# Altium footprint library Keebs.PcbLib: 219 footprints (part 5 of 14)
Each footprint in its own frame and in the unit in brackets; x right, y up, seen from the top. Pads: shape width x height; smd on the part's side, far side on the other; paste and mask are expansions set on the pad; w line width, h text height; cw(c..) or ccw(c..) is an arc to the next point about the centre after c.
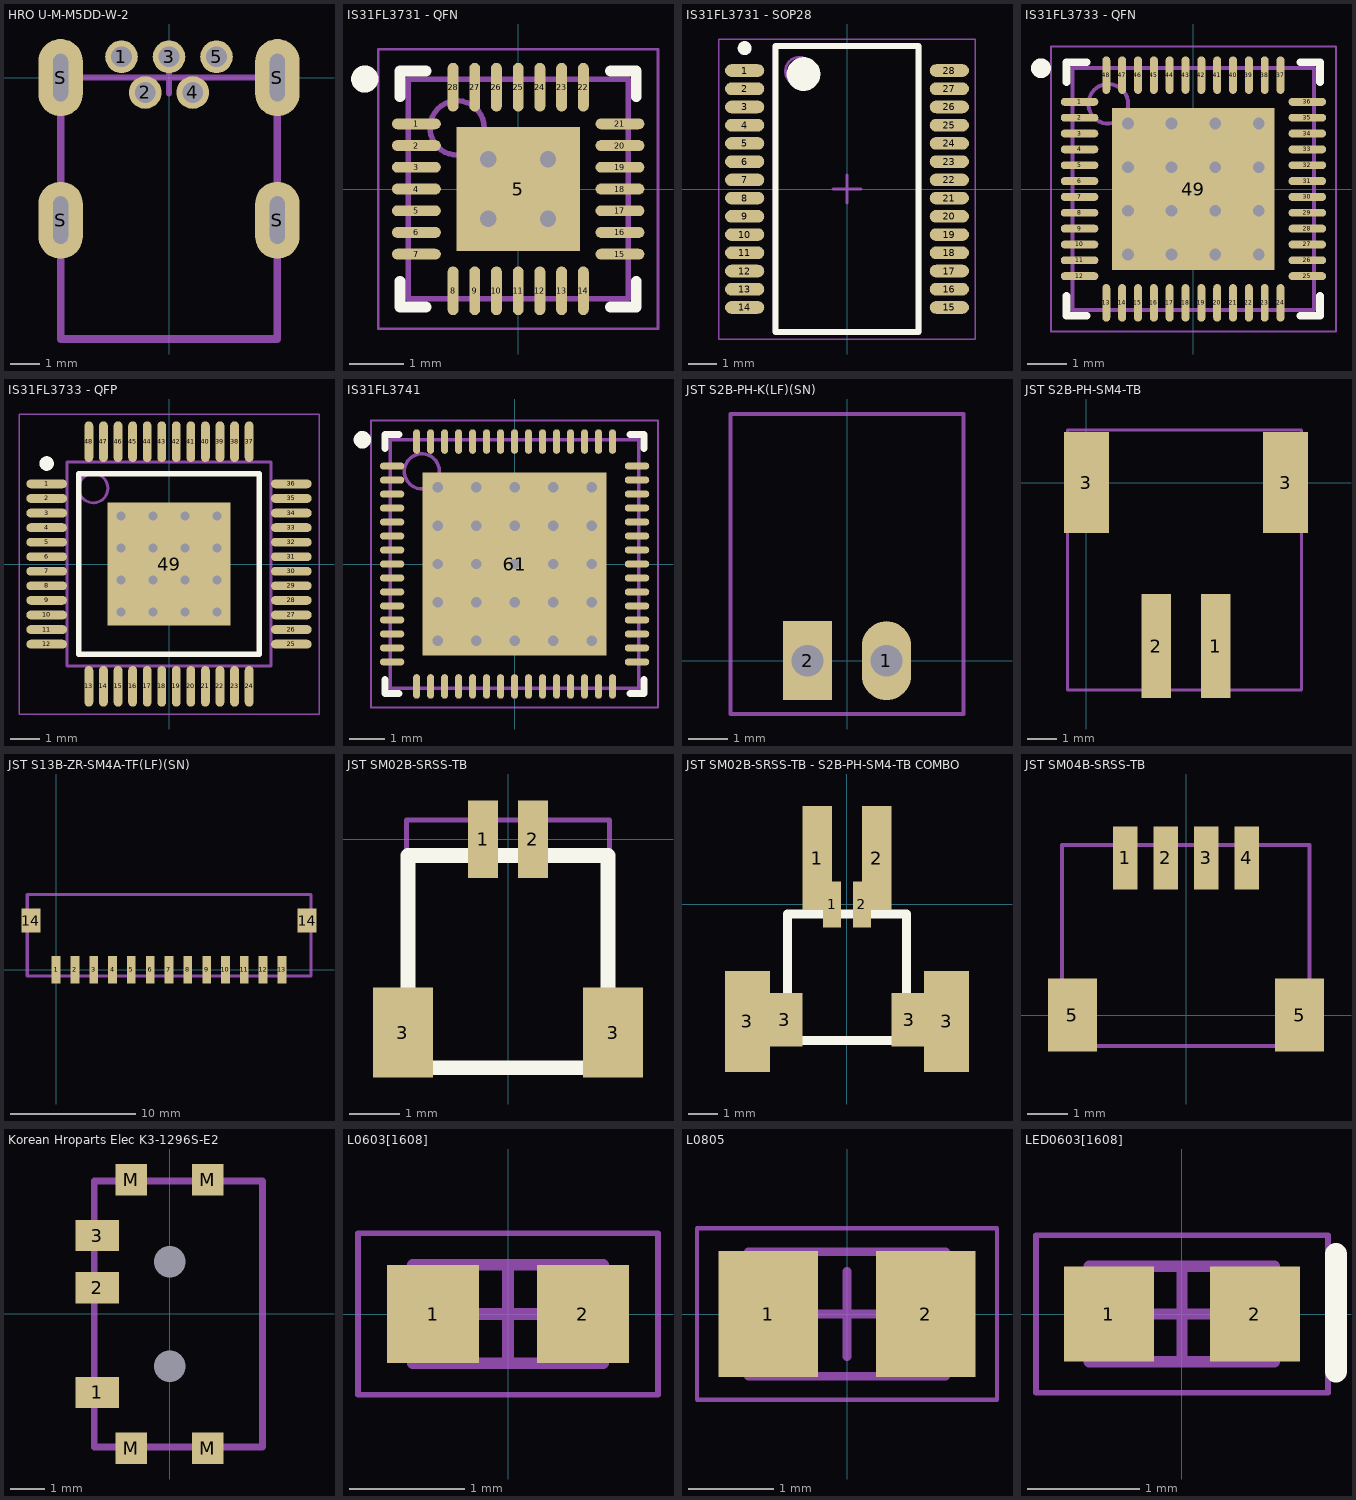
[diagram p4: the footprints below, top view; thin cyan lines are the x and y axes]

## HRO U-M-M5DD-W-2 [mm]
pads (9):
  round 1.1 hole 0.7: 1(-1.6,0.7) 2(-0.8,-0.5) 3(0,0.7) 4(0.8,-0.5) 5(1.6,0.7)
  oval 1.5x2.6 hole 0.5 slot 1.6 at 90 deg: S(-3.65,-4.8) S(-3.65,0) S(3.65,-4.8) S(3.65,0)
Mechanical 13:
  lines w0.2: -3.65,-8.8 3.65,-8.8 3.65,0 -3.65,0 -3.65,-8.8
  text ".Designator" at 1.905,-3.556 h0.35
Mechanical 15:
  lines w0.2: -0.533,0 0,0 ; 0,0.533 0,0 ; 0.533,0 0,0 ; 0,0 0,-0.533 0,0
  lines w0.254: -3.65,0 -3.65,-8.8 3.65,-8.8 3.65,0

## IS31FL3731 - QFN [mm]
height 0.8
pads (29):
  oval 0.9x0.2 smd: 1(-1.875,1.2) 2(-1.875,0.8) 3(-1.875,0.4) 4(-1.875,0) 5(-1.875,-0.4) 6(-1.875,-0.8) 7(-1.875,-1.2) 15(1.875,-1.2) 16(1.875,-0.8) 17(1.875,-0.4) 18(1.875,0) 19(1.875,0.4) 20(1.875,0.8) 21(1.875,1.2)
  rect 2.28x2.28 smd: 5(0,0)
  oval 0.2x0.9 smd: 8(-1.2,-1.875) 9(-0.8,-1.875) 10(-0.4,-1.875) 11(0,-1.875) 12(0.4,-1.875) 13(0.8,-1.875) 14(1.2,-1.875) 22(1.2,1.875) 23(0.8,1.875) 24(0.4,1.875) 25(0,1.875) 26(-0.4,1.875) 27(-0.8,1.875) 28(-1.2,1.875)
via 0.55,-0.55 diameter 0.6 hole 0.3
via -0.55,-0.55 diameter 0.6 hole 0.3
via 0.55,0.55 diameter 0.6 hole 0.3
via -0.55,0.55 diameter 0.6 hole 0.3
Top Overlay:
  circle w0.25: c-2.825,2.025 r0.125
  lines w0.2: -2.175,-1.7 -2.175,-2.175 -1.7,-2.175 ; -2.175,1.7 -2.175,2.175 -1.7,2.175 ; 1.7,-2.175 2.175,-2.175 2.175,-1.7 ; 1.7,2.175 2.175,2.175 2.175,1.7
Mechanical 13:
  circle w0.1: c-1.125,1.125 r0.5
  lines w0.1: -2.025,-2.025 2.025,-2.025 2.025,2.025 -2.025,2.025 -2.025,-2.025
  text ".Designator" at -1.905,-0.254 h0.5
Mechanical 15:
  lines w0.05: -2.575,-2.575 2.575,-2.575 2.575,2.575 -2.575,2.575 -2.575,-2.575
  lines w0.1: -0.5,0 0.5,0 ; 0,-0.5 0,0.5
3D body "IS31FL3731 - QFN.step": height 0.8, standoff 0, extent -2.026,-2.026 2.026,2.026

## IS31FL3731 - SOP28 [mm] "IS31FL3731 - SOP28"
height 1.8
pads (28):
  oval 1.4x0.45 smd: 1(-3.65,4.225) 2(-3.65,3.575) 3(-3.65,2.925) 4(-3.65,2.275) 5(-3.65,1.625) 6(-3.65,0.975) 7(-3.65,0.325) 8(-3.65,-0.325) 9(-3.65,-0.975) 10(-3.65,-1.625) 11(-3.65,-2.275) 12(-3.65,-2.925) 13(-3.65,-3.575) 14(-3.65,-4.225) 15(3.65,-4.225) 16(3.65,-3.575) 17(3.65,-2.925) 18(3.65,-2.275) 19(3.65,-1.625) 20(3.65,-0.975) 21(3.65,-0.325) 22(3.65,0.325) 23(3.65,0.975) 24(3.65,1.625) 25(3.65,2.275) 26(3.65,2.925) 27(3.65,3.575) 28(3.65,4.225)
Top Overlay:
  circle w0.25: c-3.65,5.025 r0.125
  circle w0.6: c-1.55,4.1 r0.3
  lines w0.2: -2.55,-5.1 -2.55,5.1 2.55,5.1 2.55,-5.1 -2.55,-5.1
Mechanical 13:
  circle w0.1: c-1.7,4.2 r0.5
  lines w0.1: -2.6,-5.1 -2.6,5.1 2.6,5.1 2.6,-5.1 -2.6,-5.1
  text ".Designator" at -0.254,2.159 h0.5
Mechanical 15:
  lines w0.05: -4.575,-5.35 -4.575,5.35 4.575,5.35 4.575,-5.35 -4.575,-5.35
  lines w0.1: -0.5,0 0.5,0 ; 0,-0.5 0,0.5
3D body "IS31FL3731 - SOP28.step": height 1.8, standoff 0, extent -3.9,-5.1 3.9,5.1

## IS31FL3733 - QFN [mm]
height 0.8
pads (49):
  oval 0.95x0.2 smd: 1(-2.875,2.2) 2(-2.875,1.8) 3(-2.875,1.4) 4(-2.875,1) 5(-2.875,0.6) 6(-2.875,0.2) 7(-2.875,-0.2) 8(-2.875,-0.6) 9(-2.875,-1) 10(-2.875,-1.4) 11(-2.875,-1.8) 12(-2.875,-2.2) 25(2.875,-2.2) 26(2.875,-1.8) 27(2.875,-1.4) 28(2.875,-1) 29(2.875,-0.6) 30(2.875,-0.2) 31(2.875,0.2) 32(2.875,0.6) 33(2.875,1) 34(2.875,1.4) 35(2.875,1.8) 36(2.875,2.2)
  oval 0.2x0.95 smd: 13(-2.2,-2.875) 14(-1.8,-2.875) 15(-1.4,-2.875) 16(-1,-2.875) 17(-0.6,-2.875) 18(-0.2,-2.875) 19(0.2,-2.875) 20(0.6,-2.875) 21(1,-2.875) 22(1.4,-2.875) 23(1.8,-2.875) 24(2.2,-2.875) 37(2.2,2.875) 38(1.8,2.875) 39(1.4,2.875) 40(1,2.875) 41(0.6,2.875) 42(0.2,2.875) 43(-0.2,2.875) 44(-0.6,2.875) 45(-1,2.875) 46(-1.4,2.875) 47(-1.8,2.875) 48(-2.2,2.875)
  rect 4.1x4.1 smd: 49(0,0)
via -1.65,1.65 diameter 0.6 hole 0.3
via -0.55,1.65 diameter 0.6 hole 0.3
via 0.55,1.65 diameter 0.6 hole 0.3
via 1.65,1.65 diameter 0.6 hole 0.3
via -1.65,0.55 diameter 0.6 hole 0.3
via -0.55,0.55 diameter 0.6 hole 0.3
via 0.55,0.55 diameter 0.6 hole 0.3
via 1.65,0.55 diameter 0.6 hole 0.3
via -1.65,-0.55 diameter 0.6 hole 0.3
via -0.55,-0.55 diameter 0.6 hole 0.3
via 0.55,-0.55 diameter 0.6 hole 0.3
via 1.65,-0.55 diameter 0.6 hole 0.3
via -1.65,-1.65 diameter 0.6 hole 0.3
via -0.55,-1.65 diameter 0.6 hole 0.3
via 0.55,-1.65 diameter 0.6 hole 0.3
via 1.65,-1.65 diameter 0.6 hole 0.3
Top Overlay:
  circle w0.25: c-3.85,3.05 r0.125
  lines w0.2: -3.2,-2.7 -3.2,-3.2 -2.7,-3.2 ; -3.2,2.7 -3.2,3.2 -2.7,3.2 ; 2.7,-3.2 3.2,-3.2 3.2,-2.7 ; 2.7,3.2 3.2,3.2 3.2,2.7
Mechanical 13:
  circle w0.1: c-2.15,2.15 r0.5
  lines w0.1: -3.05,-3.05 -3.05,3.05 3.05,3.05 3.05,-3.05 -3.05,-3.05
  text ".Designator" at -2.286,-0.254 h0.5
Mechanical 15:
  lines w0.05: -3.6,-3.6 -3.6,3.6 3.6,3.6 3.6,-3.6 -3.6,-3.6
  lines w0.1: -0.5,0 0.5,0 ; 0,-0.5 0,0.5
3D body "IS31FL3733 - QFN.step": height 0.8, standoff 0, extent -3.051,-3.051 3.051,3.051

## IS31FL3733 - QFP [mm]
height 1.2
pads (49):
  oval 1.4x0.3 smd: 1(-4.2,2.75) 2(-4.2,2.25) 3(-4.2,1.75) 4(-4.2,1.25) 5(-4.2,0.75) 6(-4.2,0.25) 7(-4.2,-0.25) 8(-4.2,-0.75) 9(-4.2,-1.25) 10(-4.2,-1.75) 11(-4.2,-2.25) 12(-4.2,-2.75) 25(4.2,-2.75) 26(4.2,-2.25) 27(4.2,-1.75) 28(4.2,-1.25) 29(4.2,-0.75) 30(4.2,-0.25) 31(4.2,0.25) 32(4.2,0.75) 33(4.2,1.25) 34(4.2,1.75) 35(4.2,2.25) 36(4.2,2.75)
  oval 0.3x1.4 smd: 13(-2.75,-4.2) 14(-2.25,-4.2) 15(-1.75,-4.2) 16(-1.25,-4.2) 17(-0.75,-4.2) 18(-0.25,-4.2) 19(0.25,-4.2) 20(0.75,-4.2) 21(1.25,-4.2) 22(1.75,-4.2) 23(2.25,-4.2) 24(2.75,-4.2) 37(2.75,4.2) 38(2.25,4.2) 39(1.75,4.2) 40(1.25,4.2) 41(0.75,4.2) 42(0.25,4.2) 43(-0.25,4.2) 44(-0.75,4.2) 45(-1.25,4.2) 46(-1.75,4.2) 47(-2.25,4.2) 48(-2.75,4.2)
  rect 4.21x4.21 smd: 49(0,0)
via -1.65,1.65 diameter 0.6 hole 0.3
via -0.55,1.65 diameter 0.6 hole 0.3
via 0.55,1.65 diameter 0.6 hole 0.3
via 1.65,1.65 diameter 0.6 hole 0.3
via -1.65,0.55 diameter 0.6 hole 0.3
via -0.55,0.55 diameter 0.6 hole 0.3
via 0.55,0.55 diameter 0.6 hole 0.3
via 1.65,0.55 diameter 0.6 hole 0.3
via -1.65,-0.55 diameter 0.6 hole 0.3
via -0.55,-0.55 diameter 0.6 hole 0.3
via 0.55,-0.55 diameter 0.6 hole 0.3
via 1.65,-0.55 diameter 0.6 hole 0.3
via -1.65,-1.65 diameter 0.6 hole 0.3
via -0.55,-1.65 diameter 0.6 hole 0.3
via 0.55,-1.65 diameter 0.6 hole 0.3
via 1.65,-1.65 diameter 0.6 hole 0.3
Top Overlay:
  circle w0.25: c-4.2,3.45 r0.125
  lines w0.2: -3.1,-3.1 -3.1,3.1 3.1,3.1 3.1,-3.1 -3.1,-3.1
Mechanical 13:
  circle w0.1: c-2.6,2.6 r0.5
  lines w0.1: -3.5,-3.5 -3.5,3.5 3.5,3.5 3.5,-3.5 -3.5,-3.5
  text ".Designator" at -2.667,0 h0.5
Mechanical 15:
  lines w0.05: -5.15,-5.15 -5.15,5.15 5.15,5.15 5.15,-5.15 -5.15,-5.15
  lines w0.1: -0.5,0 0.5,0 ; 0,-0.5 0,0.5
3D body "IS31FL3733 - QFP.step": height 1.2, standoff 0, extent -4.5,-4.5 4.5,4.5

## IS31FL3741 [mm]
height 0.9
pads (61):
  oval 0.7x0.2 smd: 1(-3.5,2.8) 2(-3.5,2.4) 3(-3.5,2) 4(-3.5,1.6) 5(-3.5,1.2) 6(-3.5,0.8) 7(-3.5,0.4) 8(-3.5,0) 9(-3.5,-0.4) 10(-3.5,-0.8) 11(-3.5,-1.2) 12(-3.5,-1.6) 13(-3.5,-2) 14(-3.5,-2.4) 15(-3.5,-2.8) 31(3.5,-2.8) 32(3.5,-2.4) 33(3.5,-2) 34(3.5,-1.6) 35(3.5,-1.2) 36(3.5,-0.8) 37(3.5,-0.4) 38(3.5,0) 39(3.5,0.4) 40(3.5,0.8) 41(3.5,1.2) 42(3.5,1.6) 43(3.5,2) 44(3.5,2.4) 45(3.5,2.8)
  oval 0.2x0.7 smd: 16(-2.8,-3.5) 17(-2.4,-3.5) 18(-2,-3.5) 19(-1.6,-3.5) 20(-1.2,-3.5) 21(-0.8,-3.5) 22(-0.4,-3.5) 23(0,-3.5) 24(0.4,-3.5) 25(0.8,-3.5) 26(1.2,-3.5) 27(1.6,-3.5) 28(2,-3.5) 29(2.4,-3.5) 30(2.8,-3.5) 46(2.8,3.5) 47(2.4,3.5) 48(2,3.5) 49(1.6,3.5) 50(1.2,3.5) 51(0.8,3.5) 52(0.4,3.5) 53(0,3.5) 54(-0.4,3.5) 55(-0.8,3.5) 56(-1.2,3.5) 57(-1.6,3.5) 58(-2,3.5) 59(-2.4,3.5) 60(-2.8,3.5)
  rect 5.25x5.24 smd: 61(0,0)
via -2.2,2.2 diameter 0.6 hole 0.3
via -1.1,2.2 diameter 0.6 hole 0.3
via 0,2.2 diameter 0.6 hole 0.3
via 1.1,2.2 diameter 0.6 hole 0.3
via 2.2,2.2 diameter 0.6 hole 0.3
via -2.2,1.1 diameter 0.6 hole 0.3
via -1.1,1.1 diameter 0.6 hole 0.3
via 0,1.1 diameter 0.6 hole 0.3
via 1.1,1.1 diameter 0.6 hole 0.3
via 2.2,1.1 diameter 0.6 hole 0.3
via -2.2,0 diameter 0.6 hole 0.3
via -1.1,0 diameter 0.6 hole 0.3
via 0,0 diameter 0.6 hole 0.3
via 1.1,0 diameter 0.6 hole 0.3
via 2.2,0 diameter 0.6 hole 0.3
via -2.2,-1.1 diameter 0.6 hole 0.3
via -1.1,-1.1 diameter 0.6 hole 0.3
via 0,-1.1 diameter 0.6 hole 0.3
via 1.1,-1.1 diameter 0.6 hole 0.3
via 2.2,-1.1 diameter 0.6 hole 0.3
via -2.2,-2.2 diameter 0.6 hole 0.3
via -1.1,-2.2 diameter 0.6 hole 0.3
via 0,-2.2 diameter 0.6 hole 0.3
via 1.1,-2.2 diameter 0.6 hole 0.3
via 2.2,-2.2 diameter 0.6 hole 0.3
Top Overlay:
  circle w0.25: c-4.35,3.55 r0.125
  lines w0.2: -3.7,-3.3 -3.7,-3.7 -3.3,-3.7 ; -3.7,3.3 -3.7,3.7 -3.3,3.7 ; 3.3,-3.7 3.7,-3.7 3.7,-3.3 ; 3.3,3.7 3.7,3.7 3.7,3.3
Mechanical 13:
  circle w0.1: c-2.65,2.65 r0.5
  lines w0.1: -3.55,-3.55 -3.55,3.55 3.55,3.55 3.55,-3.55 -3.55,-3.55
  text ".Designator" at -2.413,-0.127 h0.5
Mechanical 15:
  lines w0.05: -4.1,-4.1 -4.1,4.1 4.1,4.1 4.1,-4.1 -4.1,-4.1
  lines w0.1: -0.5,0 0.5,0 ; 0,-0.5 0,0.5
3D body "IS31FL3741.step": height 0.9, standoff 0, extent -3.56,-3.56 3.56,3.56

## JST S2B-PH-K(LF)(SN) [mm]
pads (2):
  oval 1.25x2 hole 0.8: 1(1,0)
  rect 1.25x2 hole 0.8: 2(-1,0)
Mechanical 13:
  lines w0.1: -2.95,-1.35 2.95,-1.35 2.95,6.25 -2.95,6.25 -2.95,-1.35
  text ".Designator" at -1.834,2.664 h0.35
3D body "S2B-PH-K-S.STEP": height 4.8, standoff -3.4, extent -2.95,-1.35 2.95,6.25

## JST S2B-PH-SM4-TB [mm]
pads (4):
  rect 1x3.5 smd: 1(4.35,-5.5) 2(2.35,-5.5)
  rect 1.5x3.4 smd: 3(0,0) 3(6.7,0)
Mechanical 13:
  lines w0.1: -0.635,-6.985 -0.635,1.778 7.239,1.778 7.239,-6.985 -0.635,-6.985
  text ".Designator" at 1.742,-2.638 h0.35
3D body "S2B-PH-SM4-TB.STEP": height 5.6, standoff 0, extent -0.648,-6.949 7.252,1.651

## JST S13B-ZR-SM4A-TF(LF)(SN) [mm]
pads (15):
  rect 0.7x2.2 smd: 1(0,0) 2(1.5,0) 3(3,0) 4(4.5,0) 5(6,0) 6(7.5,0) 7(9,0) 8(10.5,0) 9(12,0) 10(13.5,0) 11(15,0) 12(16.5,0) 13(18,0)
  rect 1.5x1.9 smd: 14(-2,3.9) 14(20,3.9)
Mechanical 13:
  lines w0.254: -2.286,-0.508 -2.286,5.969 20.32,5.969 20.32,-0.508 -2.286,-0.508
  text ".Designator" at 6.35,3.175 h0.5
3D body "S13B-ZR-SM4A-TF.STEP": height 3.7, standoff 0, extent -2.233,-0.531 20.267,5.969

## JST SM02B-SRSS-TB [mm]
pads (4):
  rect 0.6x1.55 smd: 1(-0.5,0) 2(0.5,0)
  rect 1.2x1.8 smd: 3(-2.1,-3.875) 3(2.1,-3.875)
Top Overlay:
  lines w0.3: -2,-4.575 2,-4.575 2,-0.325 -2,-0.325 -2,-4.575
Mechanical 13:
  lines w0.1: -2.032,-4.572 -2.032,0.381 2.032,0.381 2.032,-4.572 -2.032,-4.572
  text ".Designator" at -1.651,-2.286 h0.5
3D body "JST_SM02B-SRSS-TB.step": height 3, standoff 0, extent -1.994,-4.575 1.994,0.412

## JST SM02B-SRSS-TB - S2B-PH-SM4-TB COMBO [mm]
pads (8):
  rect 1x3.5 smd: 1(-1,1.563) 2(1,1.563)
  rect 0.6x1.55 smd: 1(-0.5,0) 2(0.5,0)
  rect 1.5x3.4 smd: 3(-3.35,-3.937) 3(3.35,-3.937)
  rect 1.2x1.8 smd: 3(-2.1,-3.875) 3(2.1,-3.875)
Top Overlay:
  lines w0.3: -2,-4.575 -2,-0.325 2,-0.325 2,-4.575 -2,-4.575
Mechanical 13:
  lines w0.1: -2,-4.575 2,-4.575 2,-0.325 -2,-0.325 -2,-4.575
  text ".Designator" at -1.651,-2.921 h0.5
3D body "JST_SM02B-SRSS-TB.step": height 3, standoff 0, extent -1.994,-4.575 1.994,0.412

## JST SM04B-SRSS-TB [mm]
pads (6):
  rect 0.6x1.55 smd: 1(-1.5,3.875) 2(-0.5,3.875) 3(0.5,3.875) 4(1.5,3.875)
  rect 1.2x1.8 smd: 5(-2.8,0) 5(2.8,0)
Mechanical 13:
  lines w0.1: -3.054,-0.762 3.042,-0.762 3.042,4.191 -3.054,4.191 -3.054,-0.762
  text ".Designator" at -2.673,1.524 h0.7
3D body "SM04B-SRSS-TB.STEP": height 2.96, standoff 0, extent -3.006,-0.762 2.994,4.188

## Korean Hroparts Elec K3-1296S-E2 [mm]
pads (9):
  rect 1.25x0.9 smd: 1(-2.075,-2.25) 2(-2.075,0.75) 3(-2.075,2.25)
  rect 0.9x0.9 smd: M(-1.1,-3.85) M(-1.1,3.85) M(1.1,-3.85) M(1.1,3.85)
  round 0 hole 0.9 unplated: ""(0,-1.5) ""(0,1.5)
Mechanical 13:
  lines w0.2: -2.159,-3.81 -2.159,3.81 2.667,3.81 2.667,-3.81 -2.159,-3.81
  text ".Designator" at 0.889,2.159 h0.5
3D body "EG1215AA.stp": height 1.45, standoff -0.45, extent -2.2,-3.85 2.7,3.85

## L0603[1608] [mm] "Chip Resistor, 2-Leads, Body 1,57x0,80mm, IPC Medium Density"
height 0.5
pads (2):
  rect 0.8x0.85 smd: 1(-0.65,0) 2(0.65,0)
Mechanical 13:
  lines w0.1: -0.825,-0.425 -0.825,0.425 0.825,0.425 0.825,-0.425 -0.825,-0.425
  text ".Designator" at -1.05,-0.275 h0.35
Mechanical 15:
  lines w0.05: -1.3,-0.7 -1.3,0.7 1.3,0.7 1.3,-0.7 -1.3,-0.7
  lines w0.1: -0.425,0 0.425,0 ; 0,-0.425 0,0.425
3D body: height 0.5, standoff 0, extent -0.825,-0.425 -0.525,0.425
3D body: height 0.5, standoff 0, extent 0.525,-0.425 0.825,0.425
3D body: height 0.5, standoff 0, extent -0.525,-0.425 0.525,0.425

## L0805 [mm] "based on Sunlord-GZ2012D101TF_C1015 datasheet"
height 1.02
pads (2):
  rect 1.16x1.47 smd: 1(-0.92,0) 2(0.92,0)
Mechanical 13:
  lines w0.1: -1.15,-0.725 -1.15,0.725 1.15,0.725 1.15,-0.725 -1.15,-0.725
  text ".Designator" at -0.796,-0.199 h0.35
Mechanical 15:
  lines w0.05: -1.75,-1 -1.75,1 1.75,1 1.75,-1 -1.75,-1
  lines w0.1: -0.5,0 0.5,0 ; 0,-0.5 0,0.5
3D body "L0805.step": height 1.02, standoff 0, extent -1.15,-0.725 1.15,0.725

## LED0603[1608] [mm] "Chip Resistor, 2-Leads, Body 1,57x0,80mm, IPC Medium Density"
height 0.5
pads (2):
  rect 0.8x0.85 smd: 1(-0.65,0) 2(0.65,0)
Top Overlay:
  lines w0.2: 1.372,-0.508 1.372,0.533
Mechanical 13:
  lines w0.1: -0.825,-0.425 -0.825,0.425 0.825,0.425 0.825,-0.425 -0.825,-0.425
  text ".Designator" at -1.05,-0.275 h0.35
Mechanical 15:
  lines w0.05: -1.3,-0.7 -1.3,0.7 1.3,0.7 1.3,-0.7 -1.3,-0.7
  lines w0.1: -0.425,0 0.425,0 ; 0,-0.425 0,0.425
3D body "0603 Chip SMD LED (1.6x0.8mm).STEP": height 0.8, standoff 0, extent -0.774,-0.4 0.826,0.4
